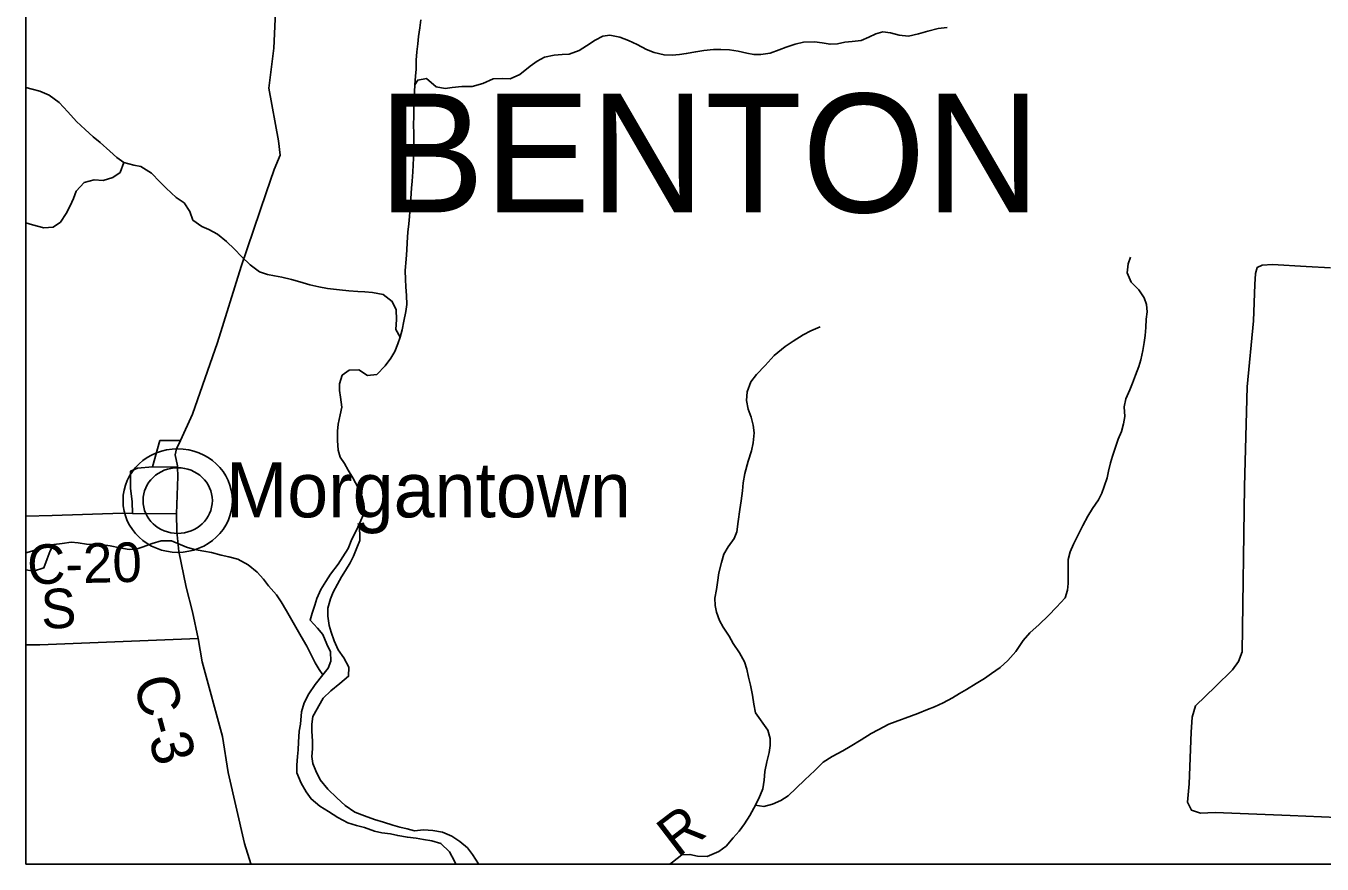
# Model space of a CAD drawing. Extents: x -139 to 835, y 0 to 440.
# Drawn here: x 67.6 to 126.7, y 185.4 to 223.6 of the extents above; entities that cross this region are included whole.
import ezdxf

# ---------------------------------------------------------------- set-up
doc = ezdxf.new("R2010")
doc.units = 0
for name, color, linetype in [('GM_X_County_Road', 7, 'Continuous'), ('GM_X_County_Road_Text', 7, 'Continuous'), ('GM_X_County_Text', 7, 'Continuous'), ('GM_X_Minor_River', 7, 'Continuous'), ('GM_X_Township_Road', 7, 'Continuous'), ('GM_X_Township_Road_Text', 7, 'Continuous'), ('GM_X_Township_Text', 7, 'Continuous'), ('GM_X_Unincorporated', 7, 'Continuous'), ('GM_X_Unincorporated_Location', 7, 'Continuous'), ('GM_X_Unincorporated_Text', 7, 'Continuous'), ('SH_Cut_Line', 7, 'Continuous')]:
    doc.layers.add(name, color=color, linetype=linetype)

msp = doc.modelspace()

# ---------------------------------------------------------------- linework, layer by layer
at = {"layer": 'GM_X_County_Road'}
for points in [[(77.839, 185.387), (77.833, 185.4), (77.551, 186.333), (76.801, 189.567), (76.54, 191.212), (75.613, 194.616), (75.44, 195.682), (75.169, 196.904), (74.89, 198.03), (74.553, 199.653), (74.462, 200.572), (74.451, 201.371), (74.508, 203.072), (74.491, 203.502), (74.488, 203.567), (74.393, 204.062), (74.446, 204.339), (74.622, 204.72), (75.174, 205.924), (76.314, 209.193), (77.393, 212.657), (78.534, 216.023), (78.901, 217.093), (79.174, 217.741), (79.105, 218.394), (78.664, 220.799), (78.888, 222.618), (79.007, 225.307)], [(127.39, 187.518), (125.239, 187.607), (121.829, 187.746), (121.145, 187.718), (120.74, 187.842), (120.555, 188.218), (120.64, 189.05), (120.73, 191.401), (120.776, 192.089), (120.921, 192.606), (121.844, 193.489), (122.613, 194.253), (122.884, 194.636), (123.054, 195.08), (123.165, 202.62), (123.28, 207.167), (123.567, 210.176), (123.63, 211.844), (123.667, 212.333), (123.742, 212.612), (123.969, 212.727), (124.434, 212.75), (125.974, 212.655), (127.086, 212.601)], [(74.451, 201.371), (72.438, 201.393), (71.992, 201.397), (68.772, 201.299), (67.578, 201.264)]]:
    msp.add_lwpolyline(points, dxfattribs=at)
at = {"layer": 'GM_X_County_Text'}
msp.add_lwpolyline([(67.578, 336.518), (67.578, 185.387), (138.399, 185.387)], dxfattribs=at)
at = {"layer": 'GM_X_Minor_River'}
for points in [[(85.589, 223.924), (85.538, 223.55), (85.487, 223.163), (85.449, 222.825), (85.41, 222.45), (85.385, 222.076), (85.372, 221.665), (85.346, 221.351), (85.321, 220.952), (85.308, 220.626), (85.282, 220.239), (85.269, 219.876), (85.269, 219.538), (85.256, 219.115), (85.268, 218.741), (85.268, 218.088), (85.255, 217.617), (85.242, 217.279), (85.229, 216.977), (85.191, 216.554), (85.165, 216.24), (85.127, 215.768), (85.101, 215.37), (85.076, 214.947), (85.037, 214.608), (84.999, 214.222), (84.961, 213.751), (84.948, 213.412), (84.922, 212.989), (84.871, 212.47), (84.896, 212.059), (84.909, 211.733), (84.934, 211.334), (84.946, 210.923), (84.908, 210.609), (84.819, 210.162), (84.742, 209.763), (84.653, 209.437), (84.539, 209.135), (84.399, 208.785), (84.221, 208.483), (83.966, 208.132), (83.585, 207.733), (83.165, 207.685), (82.759, 207.951), (82.327, 207.927), (81.996, 207.697), (81.881, 207.311), (81.881, 206.996), (81.932, 206.694), (81.982, 206.235), (81.906, 205.897), (81.817, 205.462), (81.791, 205.148), (81.791, 204.725), (81.816, 204.278), (81.918, 203.964), (82.108, 203.662), (82.273, 203.36), (82.489, 203.021), (82.73, 202.562), (82.921, 202.151), (82.997, 201.837), (83.022, 201.451), (82.793, 200.931)], [(85.321, 220.952), (85.448, 221.169), (85.855, 221.242), (86.286, 220.867), (86.706, 220.783), (87.024, 220.831), (87.456, 220.879), (87.926, 220.879), (88.422, 221.012), (88.892, 221.23), (89.337, 221.242), (89.667, 221.23), (90.112, 221.423), (90.57, 221.81), (90.9, 222.027), (91.231, 222.209), (91.676, 222.305), (92.032, 222.329), (92.362, 222.354), (92.807, 222.523), (93.15, 222.728), (93.545, 222.982), (93.888, 223.175), (94.206, 223.224), (94.663, 223.127), (95.07, 222.97), (95.451, 222.789), (95.883, 222.571), (96.226, 222.426), (96.683, 222.318), (97.052, 222.305), (97.382, 222.342), (97.7, 222.378), (98.132, 222.463), (98.501, 222.511), (98.933, 222.559), (99.276, 222.571), (99.67, 222.547), (100.064, 222.487), (100.458, 222.402), (100.776, 222.342), (101.093, 222.33), (101.526, 222.402), (101.932, 222.547), (102.25, 222.668), (102.67, 222.813), (103.038, 222.898), (103.547, 222.91), (103.902, 222.861), (104.258, 222.801), (104.589, 222.825), (104.932, 222.898), (105.262, 222.934), (105.669, 222.97), (106.025, 223.127), (106.343, 223.284), (106.661, 223.369), (107.017, 223.32), (107.41, 223.224), (107.83, 223.175), (108.287, 223.272), (108.72, 223.405), (109.19, 223.526), (109.597, 223.574)], [(84.653, 209.437), (84.45, 209.788), (84.476, 210.247), (84.463, 210.682), (84.286, 211.068), (83.879, 211.382), (83.383, 211.479), (83.04, 211.503), (82.71, 211.515), (82.303, 211.552), (81.884, 211.588), (81.337, 211.66), (80.943, 211.733), (80.524, 211.829), (80.067, 211.962), (79.685, 212.059), (79.253, 212.168), (78.91, 212.24), (78.592, 212.301), (78.237, 212.409), (77.805, 212.736), (77.411, 213.122), (77.093, 213.449), (76.725, 213.799), (76.318, 214.137), (75.925, 214.355), (75.607, 214.488), (75.188, 214.778), (75.048, 215.176), (74.794, 215.563), (74.438, 215.805), (73.968, 216.228), (73.689, 216.53), (73.308, 216.916), (72.812, 217.219), (72.495, 217.291), (72.05, 217.4), (71.732, 217.629), (71.402, 217.919), (70.97, 218.318), (70.652, 218.584), (70.284, 218.91), (69.89, 219.285), (69.484, 219.72), (69.09, 220.143), (68.645, 220.481), (68.213, 220.662), (67.857, 220.747), (67.578, 220.832)], [(72.05, 217.4), (71.884, 216.953), (71.541, 216.723), (71.096, 216.59), (70.689, 216.614), (70.232, 216.494), (69.863, 216.095), (69.748, 215.769), (69.596, 215.43), (69.418, 215.08), (69.15, 214.681), (68.82, 214.452), (68.388, 214.428), (67.879, 214.561), (67.578, 214.66)], [(117.966, 213.086), (117.852, 212.784), (117.801, 212.373), (117.991, 211.951), (118.334, 211.588), (118.588, 211.226), (118.69, 210.923), (118.715, 210.585), (118.677, 210.259), (118.664, 209.872), (118.625, 209.51), (118.587, 209.196), (118.523, 208.833), (118.434, 208.398), (118.345, 208.096), (118.192, 207.697), (118.052, 207.335), (117.925, 207.033), (117.747, 206.622), (117.67, 206.26), (117.695, 205.813), (117.644, 205.474), (117.542, 205.136), (117.402, 204.786), (117.275, 204.411), (117.135, 204), (117.046, 203.698), (116.957, 203.312), (116.893, 203.01), (116.766, 202.623), (116.651, 202.309), (116.498, 202.007), (116.219, 201.608), (116.015, 201.27), (115.786, 200.835), (115.557, 200.388), (115.366, 199.989), (115.201, 199.639), (115.112, 199.288), (115.111, 198.89), (115.124, 198.527), (115.111, 198.189), (115.085, 197.887), (114.983, 197.536), (114.589, 197.113), (114.22, 196.739), (113.788, 196.328), (113.368, 195.942), (113.063, 195.591), (112.732, 195.096), (112.364, 194.673), (112.02, 194.359), (111.613, 194.081), (111.295, 193.863), (110.914, 193.622), (110.482, 193.356), (110.164, 193.175), (109.846, 192.969), (109.414, 192.752), (109.02, 192.571), (108.702, 192.438), (108.257, 192.257)], [(103.806, 209.909), (103.374, 209.728), (103.031, 209.547), (102.573, 209.257), (102.204, 209.015), (101.708, 208.604), (101.301, 208.145), (100.907, 207.734), (100.64, 207.396), (100.475, 206.937), (100.449, 206.55), (100.525, 206.151), (100.652, 205.777), (100.753, 205.414), (100.791, 205.064), (100.753, 204.617), (100.676, 204.254), (100.524, 203.783), (100.371, 203.215), (100.294, 202.792), (100.256, 202.418), (100.205, 201.971), (100.141, 201.572), (100.065, 201.016), (100.001, 200.557), (99.886, 200.243), (99.606, 199.868), (99.416, 199.53), (99.301, 199.156), (99.186, 198.684), (99.123, 198.237), (99.072, 197.911), (98.995, 197.524), (99.02, 197.186), (99.071, 196.884), (99.211, 196.509), (99.375, 196.207), (99.655, 195.784), (99.833, 195.458), (100.125, 195.023), (100.353, 194.613), (100.455, 194.286), (100.531, 193.924), (100.632, 193.549), (100.721, 193.102), (100.784, 192.691), (100.848, 192.293)], [(82.793, 200.931), (82.64, 200.593), (82.437, 200.218), (82.271, 199.795), (82.029, 199.409), (81.826, 199.082), (81.47, 198.611), (81.253, 198.285), (81.037, 197.922), (80.846, 197.512), (80.757, 197.21), (80.63, 196.835), (80.541, 196.521), (80.871, 196.158), (81.127, 195.86), (81.301, 195.419), (81.468, 195.071), (81.48, 194.648), (81.366, 194.334), (81.124, 194.02), (80.768, 193.585), (80.488, 193.162), (80.272, 192.739), (80.144, 192.34)], [(80.661, 192.126), (81.136, 192.956), (81.479, 193.295), (81.899, 193.621), (82.293, 193.959), (82.306, 194.37), (82.078, 194.805), (81.824, 195.168), (81.633, 195.578), (81.506, 195.965), (81.405, 196.279), (81.354, 196.702), (81.354, 197.065), (81.469, 197.5), (81.596, 197.802), (81.787, 198.164), (81.965, 198.49), (82.156, 198.792), (82.36, 199.131), (82.525, 199.433), (82.665, 199.819), (82.805, 200.158), (82.793, 200.931)], [(67.578, 199.588), (67.846, 199.675), (68.189, 199.796), (68.519, 199.904), (68.85, 199.965), (69.231, 200.025), (69.638, 200.073), (69.968, 200.049), (70.337, 199.989), (70.744, 199.965), (71.087, 199.953), (71.417, 199.904), (71.862, 199.82), (72.281, 199.747), (72.599, 199.759), (72.93, 199.868), (73.336, 200.013), (73.743, 200.146), (74.213, 200.146), (74.9, 199.856), (75.268, 199.747), (75.687, 199.674), (76.043, 199.602), (76.488, 199.493), (76.831, 199.409), (77.251, 199.3), (77.721, 199.046), (78.127, 198.708), (78.419, 198.394), (78.648, 198.092), (79.004, 197.669), (79.219, 197.355), (79.461, 196.944), (79.702, 196.521), (79.956, 196.086), (80.134, 195.772), (80.388, 195.337), (80.54, 195.035), (80.768, 194.576), (80.946, 194.261), (81.124, 194.02)], [(68.85, 199.965), (68.684, 199.687), (68.544, 199.312), (68.392, 198.902), (67.921, 198.757), (67.578, 198.814)], [(80.144, 192.34), (80.102, 191.778), (80.037, 191.452), (80.01, 190.958), (79.996, 190.596), (79.97, 190.294), (79.93, 189.908), (79.929, 189.546), (80.13, 189.075), (80.357, 188.677), (80.585, 188.362), (80.977, 188.023), (81.381, 187.781), (81.799, 187.514), (82.267, 187.272), (82.66, 187.15), (83.028, 187.052), (83.484, 186.894), (83.813, 186.808), (84.206, 186.771), (84.536, 186.686), (84.979, 186.612), (85.372, 186.563), (85.715, 186.513), (86.095, 186.452), (86.5, 186.33), (86.892, 185.943), (87.119, 185.52), (87.184, 185.387)], [(96.946, 185.387), (97.062, 185.479), (97.494, 185.816), (97.862, 185.827), (98.217, 185.753), (98.648, 185.74), (99.182, 185.955), (99.512, 186.208), (99.831, 186.581), (100.111, 186.894), (100.353, 187.231), (100.595, 187.604), (100.774, 187.941), (101.004, 188.387), (101.196, 188.821), (101.248, 189.219), (101.274, 189.617), (101.365, 190.051), (101.48, 190.473), (101.52, 190.798), (101.521, 191.112), (101.421, 191.498), (100.848, 192.293)], [(100.84, 188.07), (101.243, 188.012), (101.637, 188.12), (102.018, 188.288), (102.349, 188.504), (102.705, 188.853), (103.099, 189.237), (103.557, 189.658), (103.939, 190.043), (104.346, 190.295), (104.842, 190.559), (105.172, 190.751), (105.668, 191.064), (106.125, 191.34), (106.443, 191.52), (106.939, 191.772), (108.257, 192.257)], [(88.228, 185.387), (88.222, 185.396), (87.944, 185.819), (87.717, 186.134), (87.376, 186.424), (87.009, 186.654), (86.578, 186.837), (86.135, 186.922), (85.716, 186.948), (85.297, 186.901), (84.968, 186.998), (84.638, 187.072), (84.309, 187.157), (83.891, 187.303), (83.473, 187.425), (83.017, 187.583), (82.586, 187.753), (82.143, 188.068), (81.764, 188.407), (81.347, 188.806), (80.993, 189.23), (80.805, 189.64), (80.666, 189.979), (80.617, 190.292), (80.643, 190.642), (80.657, 191.004), (80.621, 191.45), (80.622, 191.776), (80.661, 192.126)]]:
    msp.add_lwpolyline(points, dxfattribs=at)
at = {"layer": 'GM_X_Township_Road'}
for p, q in [((73.359, 203.523), (73.68, 204.719)), ((73.68, 204.719), (74.622, 204.72))]:
    msp.add_line(p, q, dxfattribs=at)
for points in [[(72.344, 203.324), (72.67, 203.454), (73.359, 203.523), (74.491, 203.502)], [(72.438, 201.393), (72.429, 201.924), (72.347, 202.54), (72.341, 203.002), (72.344, 203.324)], [(67.578, 195.389), (68.208, 195.39), (75.44, 195.682)]]:
    msp.add_lwpolyline(points, dxfattribs=at)
at = {"layer": 'GM_X_Unincorporated'}
for major_axis in [(2.493, 0), (1.581, 0)]:
    msp.add_ellipse((74.5, 201.977), major_axis=major_axis, ratio=0.948307, dxfattribs=at)
at = {"layer": 'GM_X_Unincorporated_Location'}
msp.add_line((74.5, 201.977), (74.5, 201.977), dxfattribs=at)
at = {"layer": 'SH_Cut_Line'}
msp.add_lwpolyline([(67.578, 336.518), (67.578, 185.387), (295.458, 185.387), (295.458, 319.381), (267.909, 321.538), (228.151, 324.569), (207.436, 326.102), (194.287, 327.176), (177.155, 328.576), (171.559, 329.033), (160.688, 329.921), (158.444, 330.1), (105.67, 333.828), (92.493, 334.759)], close=True, dxfattribs=at)

# ---------------------------------------------------------------- texts
at = {"layer": 'GM_X_County_Road_Text'}
for s, height, rotation, p in [('C-20', 1.8057, 1.28062, (67.653, 198.157)), ('C-3', 1.9022, 285.11771, (72.464, 193.735))]:
    msp.add_text(s, height=height, rotation=rotation, dxfattribs=at).set_placement(p)
at = {"layer": 'GM_X_Township_Road_Text'}
for s, height, rotation, p in [('S', 1.806, 2.52225, (68.3, 196.117)), ('R', 1.862, 37.43151, (97.3, 185.647))]:
    msp.add_text(s, height=height, rotation=rotation, dxfattribs=at).set_placement(p)
at = {"layer": 'GM_X_Township_Text'}
msp.add_text('BENTON', height=5.4169, rotation=0.00001, dxfattribs=at).set_placement((83.657, 215.129))
at = {"layer": 'GM_X_Unincorporated_Text'}
msp.add_text('Morgantown', height=2.5099, rotation=0.00001, dxfattribs=at).set_placement((76.702, 201.212))

doc.saveas('drawing.dxf')
